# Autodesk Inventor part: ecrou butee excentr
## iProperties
Created: 2009-10
Part Number: ecrou butee excentr
Document SubType Name: Modeling
Designer: Olivier
Density: 1 g/cm^3
Author: Olivier
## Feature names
1. Extrusion1
2. Révolution1 [Revolution]
3. Extrusion3
